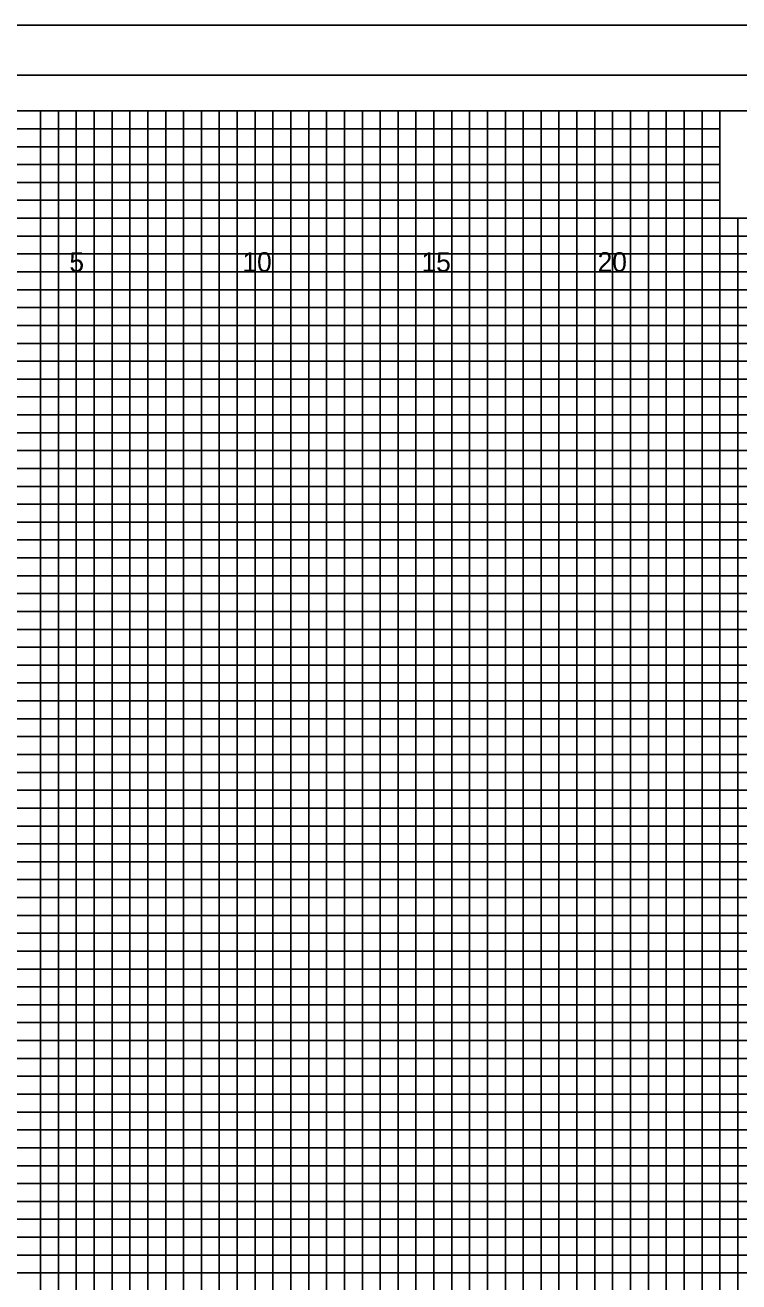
# Model space of a CAD drawing. Extents: x -4 to 103, y -2 to 138.
# Drawn here: x 54.82 to 74.78, y 32.25 to 67.4 of the extents above; entities that cross this region are included whole.
import ezdxf

# ---------------------------------------------------------------- set-up
doc = ezdxf.new("R2010")
doc.units = 0
for name, color, linetype in [('Old_Level_10', 7, 'Continuous'), ('Old_Level_16', 7, 'Continuous'), ('Old_Level_3', 7, 'Continuous'), ('Old_Level_4', 7, 'Continuous'), ('Old_Level_5', 7, 'Continuous'), ('Old_Level_8', 7, 'Continuous'), ('Prop Dimension', 7, 'Continuous'), ('Prop XS SE Text', 7, 'Continuous')]:
    doc.layers.add(name, color=color, linetype=linetype)

msp = doc.modelspace()

# ---------------------------------------------------------------- linework, layer by layer
at = {"layer": 'Old_Level_10'}
for p, q in [((56.25, 0), (56.25, 65)), ((58.75, 0), (58.75, 65)), ((61.25, 0), (61.25, 65)), ((63.75, 0), (63.75, 65)), ((66.25, 0), (66.25, 65)), ((68.75, 0), (68.75, 65)), ((71.25, 0), (71.25, 65)), ((73.75, 0), (73.75, 65)), ((0, 62.5), (74.25, 62.5)), ((0, 60), (102.5, 60)), ((0, 57.5), (102.5, 57.5)), ((0, 55), (102.5, 55)), ((0, 52.5), (102.5, 52.5)), ((0, 50), (102.5, 50)), ((0, 47.5), (102.5, 47.5)), ((0, 45), (102.5, 45)), ((0, 42.5), (102.5, 42.5)), ((0, 40), (102.5, 40)), ((0, 37.5), (102.5, 37.5)), ((0, 35), (102.5, 35)), ((0, 32.5), (102.5, 32.5))]:
    msp.add_line(p, q, dxfattribs=at)
at = {"layer": 'Old_Level_3'}
msp.add_line((-3.5, 67.4), (103.4, 67.4), dxfattribs=at)
at = {"layer": 'Old_Level_4'}
msp.add_lwpolyline([(103, 66), (-2.8, 66), (-2.8, -1), (103, -1)], close=True, dxfattribs=at)
at = {"layer": 'Old_Level_5'}
msp.add_lwpolyline([(103.4, 67.4), (-3.5, 67.4), (-3.5, -2.425), (103.4, -2.425)], close=True, dxfattribs=at)
at = {"layer": 'Old_Level_8'}
for points in [[(56.25, 0), (56.25, 65), (58.75, 65), (58.75, 0)], [(61.25, 0), (61.25, 65), (63.75, 65), (63.75, 0)], [(66.25, 0), (66.25, 65), (68.75, 65), (68.75, 0)], [(71.25, 0), (71.25, 65), (73.75, 65), (73.75, 0)], [(0, 62.5), (74.25, 62.5)], [(0, 57.5), (102.5, 57.5), (102.5, 60), (0, 60)], [(0, 52.5), (102.5, 52.5), (102.5, 55), (0, 55)], [(0, 47.5), (102.5, 47.5), (102.5, 50), (0, 50)], [(0, 42.5), (102.5, 42.5), (102.5, 45), (0, 45)], [(0, 37.5), (102.5, 37.5), (102.5, 40), (0, 40)], [(0, 32.5), (102.5, 32.5), (102.5, 35), (0, 35)]]:
    msp.add_lwpolyline(points, dxfattribs=at)
at = {"layer": 'Prop Dimension'}
for points in [[(55.25, 0), (55.25, 65), (55.75, 65), (55.75, 0)], [(56.75, 0), (56.75, 65), (57.25, 65), (57.25, 0)], [(57.75, 0), (57.75, 65), (58.25, 65), (58.25, 0)], [(59.25, 0), (59.25, 65), (59.75, 65), (59.75, 0)], [(60.25, 0), (60.25, 65), (60.75, 65), (60.75, 0)], [(61.75, 0), (61.75, 65), (62.25, 65), (62.25, 0)], [(62.75, 0), (62.75, 65), (63.25, 65), (63.25, 0)], [(64.25, 0), (64.25, 65), (64.75, 65), (64.75, 0)], [(65.25, 0), (65.25, 65), (65.75, 65), (65.75, 0)], [(66.75, 0), (66.75, 65), (67.25, 65), (67.25, 0)], [(67.75, 0), (67.75, 65), (68.25, 65), (68.25, 0)], [(69.25, 0), (69.25, 65)], [(69.25, 65), (69.75, 65), (69.75, 0)], [(70.25, 0), (70.25, 65), (70.75, 65), (70.75, 0)], [(71.75, 0), (71.75, 65), (72.25, 65), (72.25, 0)], [(72.75, 0), (72.75, 65), (73.25, 65), (73.25, 0)], [(0, 62), (0, 63), (74.25, 63), (74.25, 63.5), (0, 63.5), (0, 64), (74.25, 64), (74.25, 64.5), (0, 64.5)], [(0, 61.5), (102.5, 61.5), (102.5, 62), (0, 62)], [(74.25, 0), (74.25, 62), (74.75, 62), (74.75, 0)], [(0, 60.5), (102.5, 60.5), (102.5, 61), (0, 61)], [(0, 59), (102.5, 59), (102.5, 59.5), (0, 59.5)], [(0, 58), (102.5, 58), (102.5, 58.5), (0, 58.5)], [(0, 56.5), (102.5, 56.5), (102.5, 57), (0, 57)], [(0, 55.5), (102.5, 55.5), (102.5, 56), (0, 56)], [(0, 54), (102.5, 54), (102.5, 54.5), (0, 54.5)], [(0, 53), (102.5, 53), (102.5, 53.5), (0, 53.5)], [(0, 51.5), (102.5, 51.5), (102.5, 52), (0, 52)], [(0, 50.5), (102.5, 50.5), (102.5, 51), (0, 51)], [(0, 49), (102.5, 49), (102.5, 49.5), (0, 49.5)], [(0, 48), (102.5, 48), (102.5, 48.5), (0, 48.5)], [(0, 46.5), (102.5, 46.5), (102.5, 47), (0, 47)], [(0, 45.5), (102.5, 45.5), (102.5, 46), (0, 46)], [(0, 44), (102.5, 44), (102.5, 44.5), (0, 44.5)], [(0, 43), (102.5, 43), (102.5, 43.5), (0, 43.5)], [(0, 41.5), (102.5, 41.5), (102.5, 42), (0, 42)], [(0, 40.5), (102.5, 40.5), (102.5, 41), (0, 41)], [(0, 39), (102.5, 39), (102.5, 39.5), (0, 39.5)], [(0, 38), (102.5, 38), (102.5, 38.5), (0, 38.5)], [(0, 36.5), (102.5, 36.5), (102.5, 37), (0, 37)], [(0, 35.5), (102.5, 35.5), (102.5, 36), (0, 36)], [(0, 34), (102.5, 34), (102.5, 34.5), (0, 34.5)], [(0, 33), (102.5, 33), (102.5, 33.5), (0, 33.5)]]:
    msp.add_lwpolyline(points, dxfattribs=at)
at = {"layer": 'Prop XS SE Text'}
for points in [[(102.5, 65), (0, 65), (0, 0), (102.5, 0)], [(83.75, 65), (74.25, 65), (74.25, 62), (83.75, 62)]]:
    msp.add_lwpolyline(points, close=True, dxfattribs=at)

# ---------------------------------------------------------------- texts
at = {"layer": 'Old_Level_16'}
for s, p in [('5', (56.0574, 60.5)), ('10', (60.8971, 60.5)), ('15', (65.9057, 60.5)), ('20', (70.8312, 60.5))]:
    msp.add_text(s, height=0.55, dxfattribs=at).set_placement(p)

doc.saveas('drawing.dxf')
